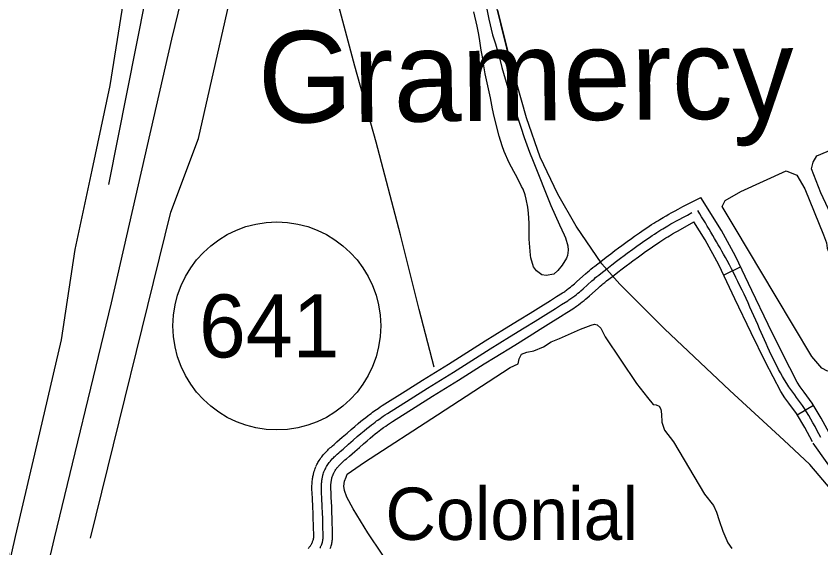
# Model space of a CAD drawing. Extents: x 3477039 to 3515015, y 546746 to 572297.
# Drawn here: x 3486477 to 3487755, y 565568 to 566412 of the extents above; entities that cross this region are included whole.
import ezdxf

# ---------------------------------------------------------------- set-up
doc = ezdxf.new("R2010")
doc.units = 0
for name, color, linetype in [('V-BLDG-IDEN', 7, 'Continuous'), ('V-DTCH-CNTR', 7, 'Continuous'), ('V-GRID-MAJR', 7, 'Continuous'), ('V-RAIL-TRAK', 7, 'Continuous'), ('V-ROAD-CNTR', 7, 'Continuous'), ('V-ROAD-IDEN', 7, 'Continuous'), ('V-SITE-VEGE', 7, 'Continuous'), ('V-TOPO-GNAM-IDEN', 7, 'Continuous'), ('V-TOPO-SHOR', 7, 'Continuous')]:
    doc.layers.add(name, color=color, linetype=linetype)

msp = doc.modelspace()

# ---------------------------------------------------------------- linework, layer by layer
at = {"layer": 'V-DTCH-CNTR'}
msp.add_lwpolyline([(3486441, 565449.8), (3486449.7, 565473.3), (3486475.5, 565586.3), (3486514.2, 565751), (3486548.9, 565898.8), (3486570.3, 566042), (3486597.2, 566167.7), (3486626.1, 566302.4), (3486645.1, 566421.8), (3486663.3, 566565.5), (3486673.8, 566695.2), (3486676.3, 566824.1), (3486671.5, 566855.2), (3486665.5, 566869.9), (3486660.1, 566883.6), (3486653.6, 566897.3), (3486650.9, 566903.4), (3486698.3, 566936.7), (3486738.1, 566962.1), (3486758.6, 566975.6)], dxfattribs=at)
at = {"layer": 'V-GRID-MAJR'}
msp.add_spline([(3486543.6, 552138.8), (3486509.2, 558197.8), (3486474.8, 564258.8), (3486440.4, 570319.8), (3486440.4, 570321.7)], degree=3, dxfattribs=at)
at = {"layer": 'V-RAIL-TRAK'}
msp.add_lwpolyline([(3487772.4, 565658.8), (3487737.2, 565700.8), (3487696, 565739.4), (3487610.2, 565818.4), (3487506.5, 565916.3), (3487435.3, 565986.9), (3487406.9, 566019.5), (3487366, 566079.1), (3487336.7, 566129.9), (3487308.7, 566188.8), (3487287.2, 566251.2), (3487263.6, 566335.3), (3487241.8, 566421.7)], dxfattribs=at)
at = {"layer": 'V-ROAD-CNTR'}
for p, q in [((3487600.2, 566001.4), (3487627.2, 566014.3)), ((3487717.1, 565779.4), (3487742.9, 565794.8))]:
    msp.add_line(p, q, dxfattribs=at)
for points in [[(3486281.3, 570321.1), (3486969.9, 567519.2), (3487264.2, 566324.9)], [(3486776, 566588.3), (3486800.3, 566690.9), (3486723.6, 566375.7), (3486627.4, 565957.6), (3486536.9, 565583.9), (3486489.2, 565381.3)], [(3487498.8, 566089.5), (3487504.2, 566092.7), (3487509, 566095.5), (3487513.2, 566097.9), (3487516.9, 566100), (3487523.4, 566103.5), (3487528.3, 566106.1), (3487535.7, 566110), (3487564, 566124.6)], [(3487767.9, 565750.8), (3487755, 565774.4), (3487740.9, 565798.1), (3487728, 565815.8), (3487722, 565823.8), (3487717, 565831.6), (3487693.6, 565876.8), (3487670.9, 565922.8), (3487645.2, 565976.8), (3487619.2, 566031.2), (3487596.6, 566072.2), (3487564, 566124.6)], [(3487506.4, 566076.6), (3487511.7, 566079.8), (3487516.4, 566082.5), (3487520.6, 566084.8), (3487524.2, 566086.8), (3487530.6, 566090.3), (3487535.4, 566092.9), (3487542.6, 566096.7), (3487549.9, 566100.5)], [(3486952.9, 565697.5), (3486953.4, 565698.6), (3486954.4, 565700.8), (3486955.2, 565702.4), (3486955.9, 565703.7), (3486956.9, 565705.4), (3486958, 565707.3), (3486959.4, 565709.3), (3486960.7, 565711.2), (3486961.9, 565713), (3486963.1, 565714.5), (3486964.3, 565715.9), (3486965.4, 565717.2), (3486966.4, 565718.4), (3486968.3, 565720.4), (3486970, 565722.2), (3486971.5, 565723.6), (3486972.8, 565724.9), (3486975, 565727), (3486976.8, 565728.5), (3486979.2, 565730.6), (3486981.7, 565732.7), (3486986.2, 565736.7), (3486994.7, 565744.1), (3487002.2, 565750.6), (3487008.7, 565756.3), (3487014.5, 565761.3), (3487019.7, 565765.6), (3487024.2, 565769.4), (3487028.3, 565772.7), (3487031.8, 565775.5), (3487035, 565778), (3487037.8, 565780.1), (3487040.3, 565781.9), (3487042.5, 565783.6), (3487046.3, 565786.3), (3487049.2, 565788.3), (3487051.5, 565789.9), (3487054.8, 565792.1), (3487058.2, 565794.2), (3487094.7, 565817.2), (3487122, 565834.4), (3487163.1, 565860.1), (3487204.1, 565885.8), (3487221.7, 565896.8), (3487252.5, 565915.9), (3487275.7, 565930.2), (3487293, 565941), (3487305.9, 565949), (3487325.3, 565961.2), (3487335, 565967.3), (3487344.6, 565973.4), (3487346.3, 565974.4), (3487347.8, 565975.4), (3487349.2, 565976.4), (3487350.6, 565977.4), (3487352, 565978.4), (3487354.6, 565980.4), (3487357.1, 565982.3), (3487359.4, 565984.2), (3487361.5, 565986), (3487363.5, 565987.7), (3487367.3, 565991), (3487381, 566003.3), (3487384.6, 566006.4), (3487387.3, 566008.8), (3487389.4, 566010.6), (3487392.6, 566013.2), (3487395.8, 566015.7), (3487405.4, 566023.2), (3487413.8, 566029.6), (3487421.2, 566035.3), (3487427.7, 566040.2), (3487433.4, 566044.4), (3487438.4, 566048.1), (3487447.2, 566054.6), (3487453.9, 566059.4), (3487458.9, 566063), (3487466.4, 566068.4), (3487474.1, 566073.7), (3487478.2, 566076.5), (3487482.2, 566079.1), (3487485.9, 566081.5), (3487489.4, 566083.8), (3487492.7, 566085.8), (3487495.8, 566087.7), (3487498.7, 566089.5)], [(3486966.6, 565691.4), (3486967, 565692.4), (3486967.8, 565694.1), (3486968.5, 565695.4), (3486969, 565696.4), (3486969.8, 565697.8), (3486970.7, 565699.3), (3486971.8, 565701), (3486972.9, 565702.5), (3486973.9, 565703.9), (3486974.9, 565705.2), (3486975.8, 565706.3), (3486976.7, 565707.4), (3486977.6, 565708.3), (3486979.2, 565710.1), (3486980.6, 565711.6), (3486981.9, 565712.9), (3486983.1, 565714), (3486985.1, 565715.8), (3486986.7, 565717.2), (3486989.1, 565719.3), (3486991.5, 565721.4), (3486996.1, 565725.3), (3487004.6, 565732.8), (3487012, 565739.3), (3487018.5, 565745), (3487024.3, 565749.9), (3487029.3, 565754.1), (3487033.7, 565757.8), (3487037.7, 565761), (3487041.1, 565763.7), (3487044.2, 565766.1), (3487046.8, 565768.1), (3487049.2, 565769.9), (3487051.3, 565771.4), (3487054.9, 565774), (3487057.7, 565776), (3487059.8, 565777.4), (3487063, 565779.5), (3487066.2, 565781.6), (3487102.7, 565804.5), (3487130, 565821.7), (3487171, 565847.4), (3487212.1, 565873.1), (3487229.6, 565884.1), (3487260.4, 565903.2), (3487283.6, 565917.5), (3487300.9, 565928.2), (3487313.9, 565936.3), (3487333.3, 565948.5), (3487343, 565954.6), (3487352.7, 565960.7), (3487354.5, 565961.9), (3487356.2, 565963), (3487357.8, 565964.1), (3487359.4, 565965.3), (3487360.9, 565966.4), (3487363.8, 565968.5), (3487366.4, 565970.6), (3487368.9, 565972.6), (3487371.2, 565974.5), (3487373.3, 565976.4), (3487377.3, 565979.8), (3487391, 565992.1), (3487394.4, 565995.1), (3487397, 565997.4), (3487399, 565999), (3487402, 566001.5), (3487405, 566003.9), (3487414.6, 566011.3), (3487422.9, 566017.7), (3487430.3, 566023.3), (3487436.7, 566028.2), (3487442.4, 566032.4), (3487447.3, 566036.1), (3487456.1, 566042.5), (3487462.6, 566047.2), (3487467.6, 566050.8), (3487475.1, 566056.1), (3487482.6, 566061.3), (3487486.6, 566064.1), (3487490.4, 566066.6), (3487494, 566068.9), (3487497.4, 566071.1), (3487500.6, 566073.1), (3487503.6, 566074.9), (3487506.4, 566076.6)], [(3487514.1, 566063.7), (3487519.3, 566066.8), (3487523.9, 566069.5), (3487527.9, 566071.7), (3487552.9, 566085.7)], [(3487741.5, 565736.5), (3487729, 565759.6), (3487715.9, 565781.5), (3487703.9, 565797.9), (3487697.2, 565806.7), (3487691, 565816.7), (3487666.9, 565863.2), (3487643.9, 565909.8), (3487618.2, 565963.9), (3487592.5, 566017.5), (3487570.7, 566057.1), (3487552.9, 566085.7)], [(3486980.3, 565685.3), (3486980.7, 565686.2), (3486981.3, 565687.5), (3486981.8, 565688.5), (3486982.1, 565689.1), (3486982.8, 565690.3), (3486983.4, 565691.3), (3486984.3, 565692.6), (3486985.1, 565693.8), (3486985.9, 565694.9), (3486986.6, 565695.8), (3486987.4, 565696.7), (3486988.1, 565697.6), (3486988.7, 565698.3), (3486990.1, 565699.8), (3486991.3, 565701), (3486992.4, 565702.1), (3486993.3, 565703), (3486995.2, 565704.7), (3486996.6, 565706), (3486998.9, 565708), (3487001.3, 565710), (3487005.9, 565714), (3487014.5, 565721.5), (3487021.9, 565728), (3487028.4, 565733.6), (3487034, 565738.5), (3487038.9, 565742.6), (3487043.2, 565746.2), (3487047, 565749.3), (3487050.4, 565751.9), (3487053.3, 565754.2), (3487055.9, 565756.1), (3487058.1, 565757.8), (3487060.1, 565759.3), (3487063.6, 565761.8), (3487066.2, 565763.6), (3487068.2, 565765), (3487071.2, 565767), (3487074.3, 565768.9), (3487110.6, 565791.8), (3487138, 565809), (3487179, 565834.7), (3487220, 565860.4), (3487237.6, 565871.3), (3487268.4, 565890.4), (3487291.5, 565904.7), (3487308.8, 565915.5), (3487321.8, 565923.6), (3487341.3, 565935.8), (3487351, 565941.9), (3487360.8, 565948.1), (3487362.7, 565949.3), (3487364.6, 565950.6), (3487366.5, 565951.9), (3487368.2, 565953.1), (3487369.9, 565954.3), (3487373, 565956.7), (3487375.8, 565958.9), (3487378.5, 565961.1), (3487380.9, 565963.1), (3487383.1, 565965), (3487387.2, 565968.6), (3487400.9, 565980.9), (3487404.3, 565983.8), (3487406.8, 565986), (3487408.6, 565987.5), (3487411.4, 565989.8), (3487414.3, 565992.1), (3487423.7, 565999.4), (3487432, 566005.8), (3487439.3, 566011.3), (3487445.7, 566016.2), (3487451.3, 566020.4), (3487456.2, 566024), (3487464.9, 566030.4), (3487471.4, 566035.1), (3487476.3, 566038.6), (3487483.7, 566043.8), (3487491.1, 566049), (3487495, 566051.6), (3487498.7, 566054.1), (3487502.1, 566056.3), (3487505.4, 566058.4), (3487508.5, 566060.3), (3487511.4, 566062.1), (3487514.2, 566063.8)], [(3487855.5, 565568.6), (3487804, 565648.3), (3487742.5, 565734.9)], [(3486940.2, 565567.4), (3486941.3, 565568.7), (3486942.3, 565569.8), (3486943.1, 565570.8), (3486943.9, 565571.8), (3486944.6, 565572.8), (3486945.1, 565573.7), (3486945.7, 565574.5), (3486946.1, 565575.3), (3486946.5, 565576.1), (3486946.9, 565576.7), (3486947.2, 565577.4), (3486947.4, 565578), (3486947.6, 565578.5), (3486948.1, 565579.6), (3486948.4, 565580.5), (3486948.6, 565581.3), (3486948.8, 565582), (3486948.9, 565582.5), (3486949, 565582.9), (3486949.1, 565583.9), (3486949.2, 565584.6), (3486949.2, 565584.9), (3486949.2, 565585.7), (3486949.3, 565586.5), (3486949.2, 565591), (3486949, 565599.1), (3486948.8, 565605.2), (3486948.5, 565614.4), (3486948.2, 565623.5), (3486947.8, 565633), (3486947.1, 565647.3), (3486946.8, 565654.6), (3486946.5, 565661.9), (3486946.5, 565664.6), (3486946.5, 565667.2), (3486946.6, 565669.7), (3486946.7, 565672.1), (3486946.9, 565674.3), (3486947.2, 565676.3), (3486947.4, 565678.3), (3486947.7, 565680.1), (3486948, 565681.8), (3486948.4, 565683.4), (3486948.7, 565685), (3486949.1, 565686.4), (3486949.4, 565687.8), (3486950.1, 565690.2), (3486950.9, 565692.3), (3486951.5, 565694.2), (3486952.2, 565695.9), (3486952.7, 565697.2)], [(3486959.2, 565568), (3486959.8, 565569.1), (3486960.3, 565570.2), (3486960.8, 565571.2), (3486961.2, 565572.1), (3486961.6, 565573), (3486962.2, 565574.6), (3486962.7, 565576.1), (3486963.1, 565577.4), (3486963.3, 565578.5), (3486963.6, 565579.5), (3486963.7, 565580.4), (3486964, 565581.9), (3486964.1, 565583.1), (3486964.2, 565584), (3486964.2, 565585.3), (3486964.3, 565586.6), (3486964.2, 565591.3), (3486964, 565599.5), (3486963.8, 565605.6), (3486963.5, 565614.9), (3486963.2, 565624.1), (3486962.8, 565633.7), (3486962.1, 565648), (3486961.8, 565655.2), (3486961.5, 565662.3), (3486961.5, 565664.7), (3486961.5, 565666.9), (3486961.6, 565669), (3486961.7, 565671), (3486961.9, 565672.8), (3486962, 565674.5), (3486962.3, 565676.1), (3486962.5, 565677.6), (3486962.8, 565679), (3486963, 565680.3), (3486963.3, 565681.5), (3486963.6, 565682.6), (3486963.9, 565683.7), (3486964.5, 565685.7), (3486965, 565687.4), (3486965.6, 565688.9), (3486966.1, 565690.3), (3486966.6, 565691.4)], [(3486975.5, 565567.4), (3486976.4, 565569.6), (3486977, 565571.6), (3486977.5, 565573.4), (3486977.9, 565575), (3486978.3, 565576.5), (3486978.5, 565577.8), (3486978.8, 565579.9), (3486979, 565581.6), (3486979.2, 565583), (3486979.2, 565584.9), (3486979.3, 565586.7), (3486979.2, 565591.6), (3486979, 565599.9), (3486978.8, 565606.1), (3486978.5, 565615.4), (3486978.1, 565624.7), (3486977.8, 565634.3), (3486977.1, 565648.6), (3486976.8, 565655.8), (3486976.5, 565662.8), (3486976.5, 565664.8), (3486976.5, 565666.6), (3486976.6, 565668.3), (3486976.7, 565669.9), (3486976.8, 565671.3), (3486976.9, 565672.6), (3486977.1, 565673.9), (3486977.3, 565675), (3486977.5, 565676.1), (3486977.7, 565677.1), (3486977.9, 565678), (3486978.1, 565678.9), (3486978.3, 565679.7), (3486978.8, 565681.2), (3486979.2, 565682.5), (3486979.6, 565683.6), (3486980, 565684.6), (3486980.4, 565685.6)]]:
    msp.add_lwpolyline(points, dxfattribs=at)
msp.add_spline([(3487754.7, 565743.6), (3487728.4, 565789.8), (3487704, 565824.2), (3487657.4, 565916.3), (3487605.8, 566024.3), (3487559.3, 566103.8)], degree=3, dxfattribs=at)
at = {"layer": 'V-ROAD-IDEN'}
msp.add_circle((3486890.7, 565920.7), 165, dxfattribs=at)
at = {"layer": 'V-SITE-VEGE'}
msp.add_lwpolyline([(3487224, 566423.3), (3487227.4, 566407.7), (3487233.4, 566382.9), (3487237.9, 566368.4), (3487244.1, 566346.1), (3487248.2, 566330.6), (3487257.5, 566298.4), (3487264.8, 566275.9), (3487270.2, 566260), (3487278.1, 566236.2), (3487283.6, 566220), (3487292.1, 566196.5), (3487297.7, 566182), (3487326, 566112.1), (3487339.7, 566080.9), (3487347.1, 566065.3), (3487349.3, 566060.4), (3487353, 566047.8), (3487353.5, 566040.9), (3487352.3, 566032.4), (3487350.6, 566028.1), (3487344, 566017.2), (3487337, 566008.6), (3487330.6, 566002.9), (3487318.5, 566001), (3487311.3, 566002), (3487302.9, 566007.9), (3487298.5, 566014.6), (3487294.2, 566028.6), (3487293.3, 566033.2), (3487291.4, 566058.5), (3487291.6, 566073.1), (3487291.5, 566083.9), (3487290.6, 566099.5), (3487289.4, 566109.2), (3487286.9, 566121.8), (3487285, 566128.7), (3487281.9, 566137.6), (3487279.2, 566141.8), (3487272.1, 566156.5), (3487267.2, 566165.8), (3487259.8, 566179.5), (3487251.8, 566197.5), (3487248.6, 566206.5), (3487243.8, 566221.9), (3487236, 566253), (3487233.1, 566265.1), (3487229.8, 566282.8), (3487221.7, 566320.9), (3487218.8, 566336.9), (3487217.2, 566348), (3487215.1, 566358.5), (3487213.3, 566373.1), (3487211.7, 566383), (3487209.1, 566396.4), (3487203.8, 566419.3)], dxfattribs=at)
at = {"layer": 'V-TOPO-SHOR'}
for points in [[(3487140.3, 565855), (3487116.9, 565947), (3487087.3, 566065.5), (3487048.6, 566212.2), (3487014.8, 566333.1), (3486985, 566444.5), (3486955.4, 566567.6), (3486915.7, 566709.2), (3486883.6, 566816.8), (3486866.9, 566875.8), (3486858.5, 566918.8), (3486853.3, 566953.6)], [(3486624.1, 566145.2), (3486697, 566513.3), (3486704.3, 566753.9), (3486715.3, 566914.2)], [(3486595, 565584), (3486722.5, 566101.5), (3486766.3, 566218.1), (3486835.5, 566524.3), (3486857.4, 566775.7), (3486861, 566859.6)], [(3487858.2, 565905.5), (3487813.3, 566006.4), (3487754.6, 566132.2), (3487739.7, 566170.2), (3487742.2, 566180.7), (3487748.2, 566190.7), (3487811.1, 566217.1), (3487819.4, 566220), (3487830.6, 566219.2), (3487841.1, 566208.5), (3487906.2, 566025.4), (3487933.5, 565942.4), (3487935.1, 565923.5), (3487927.3, 565916.5), (3487906, 565905.6), (3487888.7, 565896.3), (3487879.3, 565894.1), (3487869.8, 565895.4), (3487865.7, 565897.2), (3487859.3, 565902), (3487858.2, 565905.5)], [(3487764.8, 566044.2), (3487817, 565916.7), (3487829, 565886.4), (3487827.2, 565882.3), (3487817.6, 565870), (3487765.4, 565848.8), (3487756, 565853.6), (3487740.3, 565872.1), (3487681.9, 565969.6), (3487618.8, 566076), (3487598, 566110.5), (3487602.8, 566119.9), (3487627.8, 566134.3), (3487699.6, 566167.1), (3487716.6, 566159.8), (3487729.3, 566138.4), (3487758.6, 566065.5), (3487763.7, 566052.4), (3487764.8, 566044.2)], [(3487080.6, 565524.7), (3487035.3, 565592.5), (3487011.7, 565630.5), (3487001.6, 565648.9), (3486998, 565659.3), (3486997.1, 565666.4), (3486998.1, 565674.4), (3487000.6, 565680.9), (3487002.5, 565685.6), (3487030, 565704.6), (3487145.7, 565779.4), (3487261.4, 565854.7), (3487273.7, 565860.7), (3487275.7, 565868.7), (3487279.5, 565875.7), (3487287.5, 565879.3), (3487298.9, 565881.1), (3487314, 565887.5), (3487326.3, 565895.3), (3487339.6, 565900.8), (3487373.1, 565915.5), (3487389.7, 565921.9), (3487395.3, 565923.7), (3487399.6, 565922.2), (3487405.1, 565917), (3487412, 565903.3), (3487462, 565829.3), (3487479.1, 565807), (3487488.4, 565796), (3487493.1, 565795.5), (3487497.8, 565793.1), (3487500.5, 565788.4), (3487501.8, 565780.8), (3487502.2, 565768.1), (3487506.2, 565755.4), (3487520.6, 565736.8), (3487569.9, 565653.5), (3487584.3, 565635.9), (3487588.9, 565625), (3487593, 565611.8), (3487598.9, 565594.8), (3487606.7, 565576.3), (3487613.1, 565567.3)]]:
    msp.add_lwpolyline(points, dxfattribs=at)

# ---------------------------------------------------------------- texts
at = {"layer": 'V-BLDG-IDEN'}
msp.add_text('Colonial', height=83, dxfattribs=at).set_placement((3487063.2, 565581.1))
at = {"layer": 'V-ROAD-IDEN'}
msp.add_text('641', height=100, dxfattribs=at).set_placement((3486767.1, 565870.7))
at = {"layer": 'V-TOPO-GNAM-IDEN'}
msp.add_text('Gramercy', height=145, rotation=0.4893, dxfattribs=at).set_placement((3486861, 566243))

doc.saveas('drawing.dxf')
